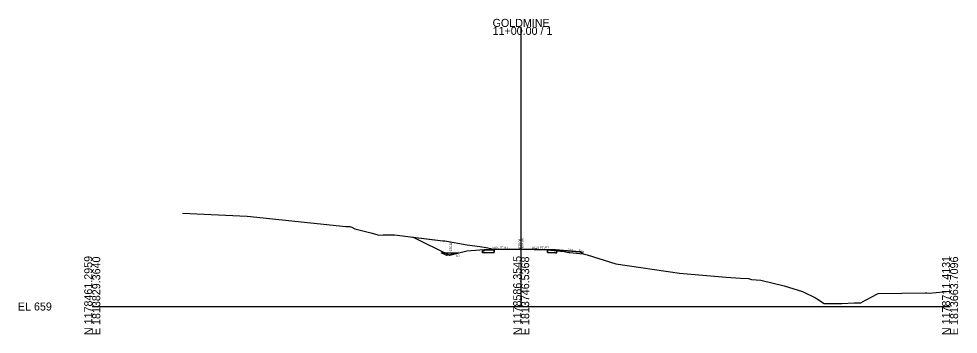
# Model space of a CAD drawing. Extents: x -26 to 1603, y -10 to 1590.
# Drawn here: x 1274.3 to 1602.8, y 490.3 to 600.7 of the extents above; entities that cross this region are included whole.
import ezdxf

# ---------------------------------------------------------------- set-up
doc = ezdxf.new("R2010")
doc.units = 0
for name, color, linetype in [('Default', 7, 'Continuous'), ('RD_GPK_XS_Cell', 7, 'Continuous'), ('RD_XS_Base', 7, 'Continuous'), ('RD_XS_EarthShd', 7, 'Continuous'), ('RD_XS_ExGround', 7, 'Continuous'), ('RD_XS_GR', 7, 'Continuous'), ('RD_XS_Misc_Line', 7, 'Continuous'), ('RD_XS_Pave', 7, 'Continuous'), ('RD_XS_TieSlope', 7, 'Continuous'), ('RD_XS_TX_Elev_EX', 7, 'Continuous'), ('RD_XS_TX_Elev_PR', 7, 'Continuous'), ('RD_XS_TX_Slope', 7, 'Continuous')]:
    doc.layers.add(name, color=color, linetype=linetype)

msp = doc.modelspace()

# ---------------------------------------------------------------- linework, layer by layer
at = {"layer": 'Default'}
for p, q in [((1450, 520.08), (1437, 519.81)), ((1461.95, 519.83), (1450, 520.08))]:
    msp.add_line(p, q, dxfattribs=at)
at = {"layer": 'RD_GPK_XS_Cell'}
for p, q in [((1450, 500), (1450, 597.82)), ((1300, 500), (1450, 500)), ((1450, 500), (1600, 500))]:
    msp.add_line(p, q, dxfattribs=at)
at = {"layer": 'RD_XS_Base'}
for p, q in [((1440.5, 518.88), (1440.5, 519.88)), ((1459.24, 518.89), (1459.24, 519.78)), ((1437, 518.81), (1440.5, 518.88)), ((1461.95, 518.83), (1459.24, 518.89))]:
    msp.add_line(p, q, dxfattribs=at)
at = {"layer": 'RD_XS_EarthShd'}
for p, q in [((1437, 519.81), (1431, 519.31)), ((1461.95, 519.83), (1470.53, 519.12))]:
    msp.add_line(p, q, dxfattribs=at)
at = {"layer": 'RD_XS_ExGround'}
msp.add_lwpolyline([(1331.56, 532.61), (1354.16, 531.64), (1388.64, 528.03), (1390.05, 527.97), (1390.77, 527.79), (1391.88, 527.14), (1397.47, 525.77), (1399.54, 525.17), (1400.08, 524.93), (1401.73, 525.07), (1404.85, 525.08), (1405.74, 525.04), (1422.56, 523.01), (1423.32, 522.92), (1431.14, 521.61), (1435.58, 521), (1437.7, 520.64), (1438.34, 520.56), (1439.82, 520.12), (1440.5, 520.01), (1449.14, 520.08), (1449.76, 520.09), (1459.24, 519.78), (1465.03, 519.27), (1466.65, 518.92), (1466.98, 518.88), (1471.73, 518.48), (1473.07, 518.07), (1483.07, 514.98), (1505.41, 511.69), (1521.66, 510.25), (1526.73, 509.91), (1529.55, 509.76), (1530.59, 509.49), (1533.8, 509.18), (1541.98, 507.22), (1548.44, 505.23), (1552.89, 503.02), (1556.01, 501.09), (1559.86, 501.09), (1562.11, 501.11), (1566.49, 501.28), (1568.74, 501.29), (1570.44, 502.18), (1574.89, 504.54), (1591.37, 504.75), (1591.89, 504.74), (1592.72, 504.72), (1600, 505.38)], dxfattribs=at)
at = {"layer": 'RD_XS_GR'}
for p, q in [((1424, 517.79), (1422, 518.79)), ((1422, 518.79), (1428, 518.79)), ((1428, 518.79), (1424, 517.79))]:
    msp.add_line(p, q, dxfattribs=at)
at = {"layer": 'RD_XS_Misc_Line'}
for points in [[(1449.76, 520.09), (1450.18, 520.08), (1450, 520.08), (1440.5, 519.88), (1437, 519.81), (1431, 519.31), (1425, 517.81), (1412.07, 524.28), (1422.56, 523.01), (1423.32, 522.92), (1431.14, 521.61), (1435.58, 521), (1437.7, 520.64), (1438.34, 520.56), (1439.82, 520.12), (1440.5, 520.01), (1449.14, 520.08)], [(1437, 518.81), (1436.5, 518.8), (1436.5, 519.47), (1437, 519.48), (1437, 519.81), (1440.5, 519.88), (1440.5, 518.88)], [(1461.95, 519.54), (1461.95, 519.83), (1450.18, 520.08), (1459.24, 519.78)], [(1462.45, 519.49), (1461.95, 519.5), (1461.95, 519.54), (1459.24, 519.78), (1459.24, 518.89), (1461.95, 518.83), (1462.45, 518.82)], [(1461.95, 519.54), (1462.45, 519.49), (1465.03, 519.27), (1466.65, 518.92), (1466.98, 518.88), (1471.73, 518.48), (1470.53, 519.12), (1461.95, 519.83)], [(1461.95, 519.54), (1462.45, 519.49), (1461.95, 519.5)]]:
    msp.add_lwpolyline(points, close=True, dxfattribs=at)
at = {"layer": 'RD_XS_Pave'}
for p, q in [((1436.5, 519.47), (1437, 519.48)), ((1436.5, 518.8), (1436.5, 519.47)), ((1437, 519.48), (1437, 519.81)), ((1461.95, 519.5), (1461.95, 519.83)), ((1462.45, 519.49), (1461.95, 519.5)), ((1462.45, 518.82), (1462.45, 519.49)), ((1437, 518.81), (1436.5, 518.8)), ((1461.95, 518.83), (1462.45, 518.82))]:
    msp.add_line(p, q, dxfattribs=at)
at = {"layer": 'RD_XS_TieSlope'}
msp.add_line((1471.73, 518.48), (1470.53, 519.12), dxfattribs=at)

# ---------------------------------------------------------------- texts
at = {"layer": 'Default'}
msp.add_text(' 679.08', height=0.8, rotation=90, dxfattribs=at).set_placement((1450.91, 520.08))
at = {"layer": 'RD_GPK_XS_Cell'}
for s, p in [('GOLDMINE', (1440, 597.82)), ('11+00.00 / 1', (1440, 595.02)), ('EL 659', (1274, 498.6))]:
    msp.add_text(s, height=2.8, dxfattribs=at).set_placement(p)
for s, p in [('N 1178461.2959', (1300, 490)), ('E 1813829.3640', (1302.8, 490)), ('N 1178586.3545', (1450, 490)), ('E 1813746.5368', (1452.8, 490)), ('N 1178711.4131', (1600, 490)), ('E 1813663.7096', (1602.8, 490))]:
    msp.add_text(s, height=2.8, rotation=90, dxfattribs=at).set_placement(p)
at = {"layer": 'RD_XS_TX_Elev_EX'}
msp.add_text('679.08', height=0.8, rotation=90, dxfattribs=at).set_placement((1449.84, 520.3))
at = {"layer": 'RD_XS_TX_Elev_PR'}
msp.add_text('676.81', height=0.8, rotation=90, dxfattribs=at).set_placement((1425.8, 519.3))
at = {"layer": 'RD_XS_TX_Slope'}
for s, rotation, p in [('0.021 FT./FT.', 1.1916, (1439.71, 520.12)), ('0.021 FT./FT.', 358.8084, (1453.72, 520.25)), ('12:1', 354.4902, (1466.15, 519.53)), ('VAR.', 333.1331, (1469.9, 519.49)), ('4:1', 14.0362, (1427.29, 517.26))]:
    msp.add_text(s, height=0.75, rotation=rotation, dxfattribs=at).set_placement(p)

doc.saveas('drawing.dxf')
